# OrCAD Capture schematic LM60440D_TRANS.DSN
size E; title: LM60440D 3.8-V to 36-V, 4-A Ultra-Small Synchronous; rev: 1.0; note: Datasheet:SNVSBN5     EVM:NA; note: Synchronous Step Down Converter
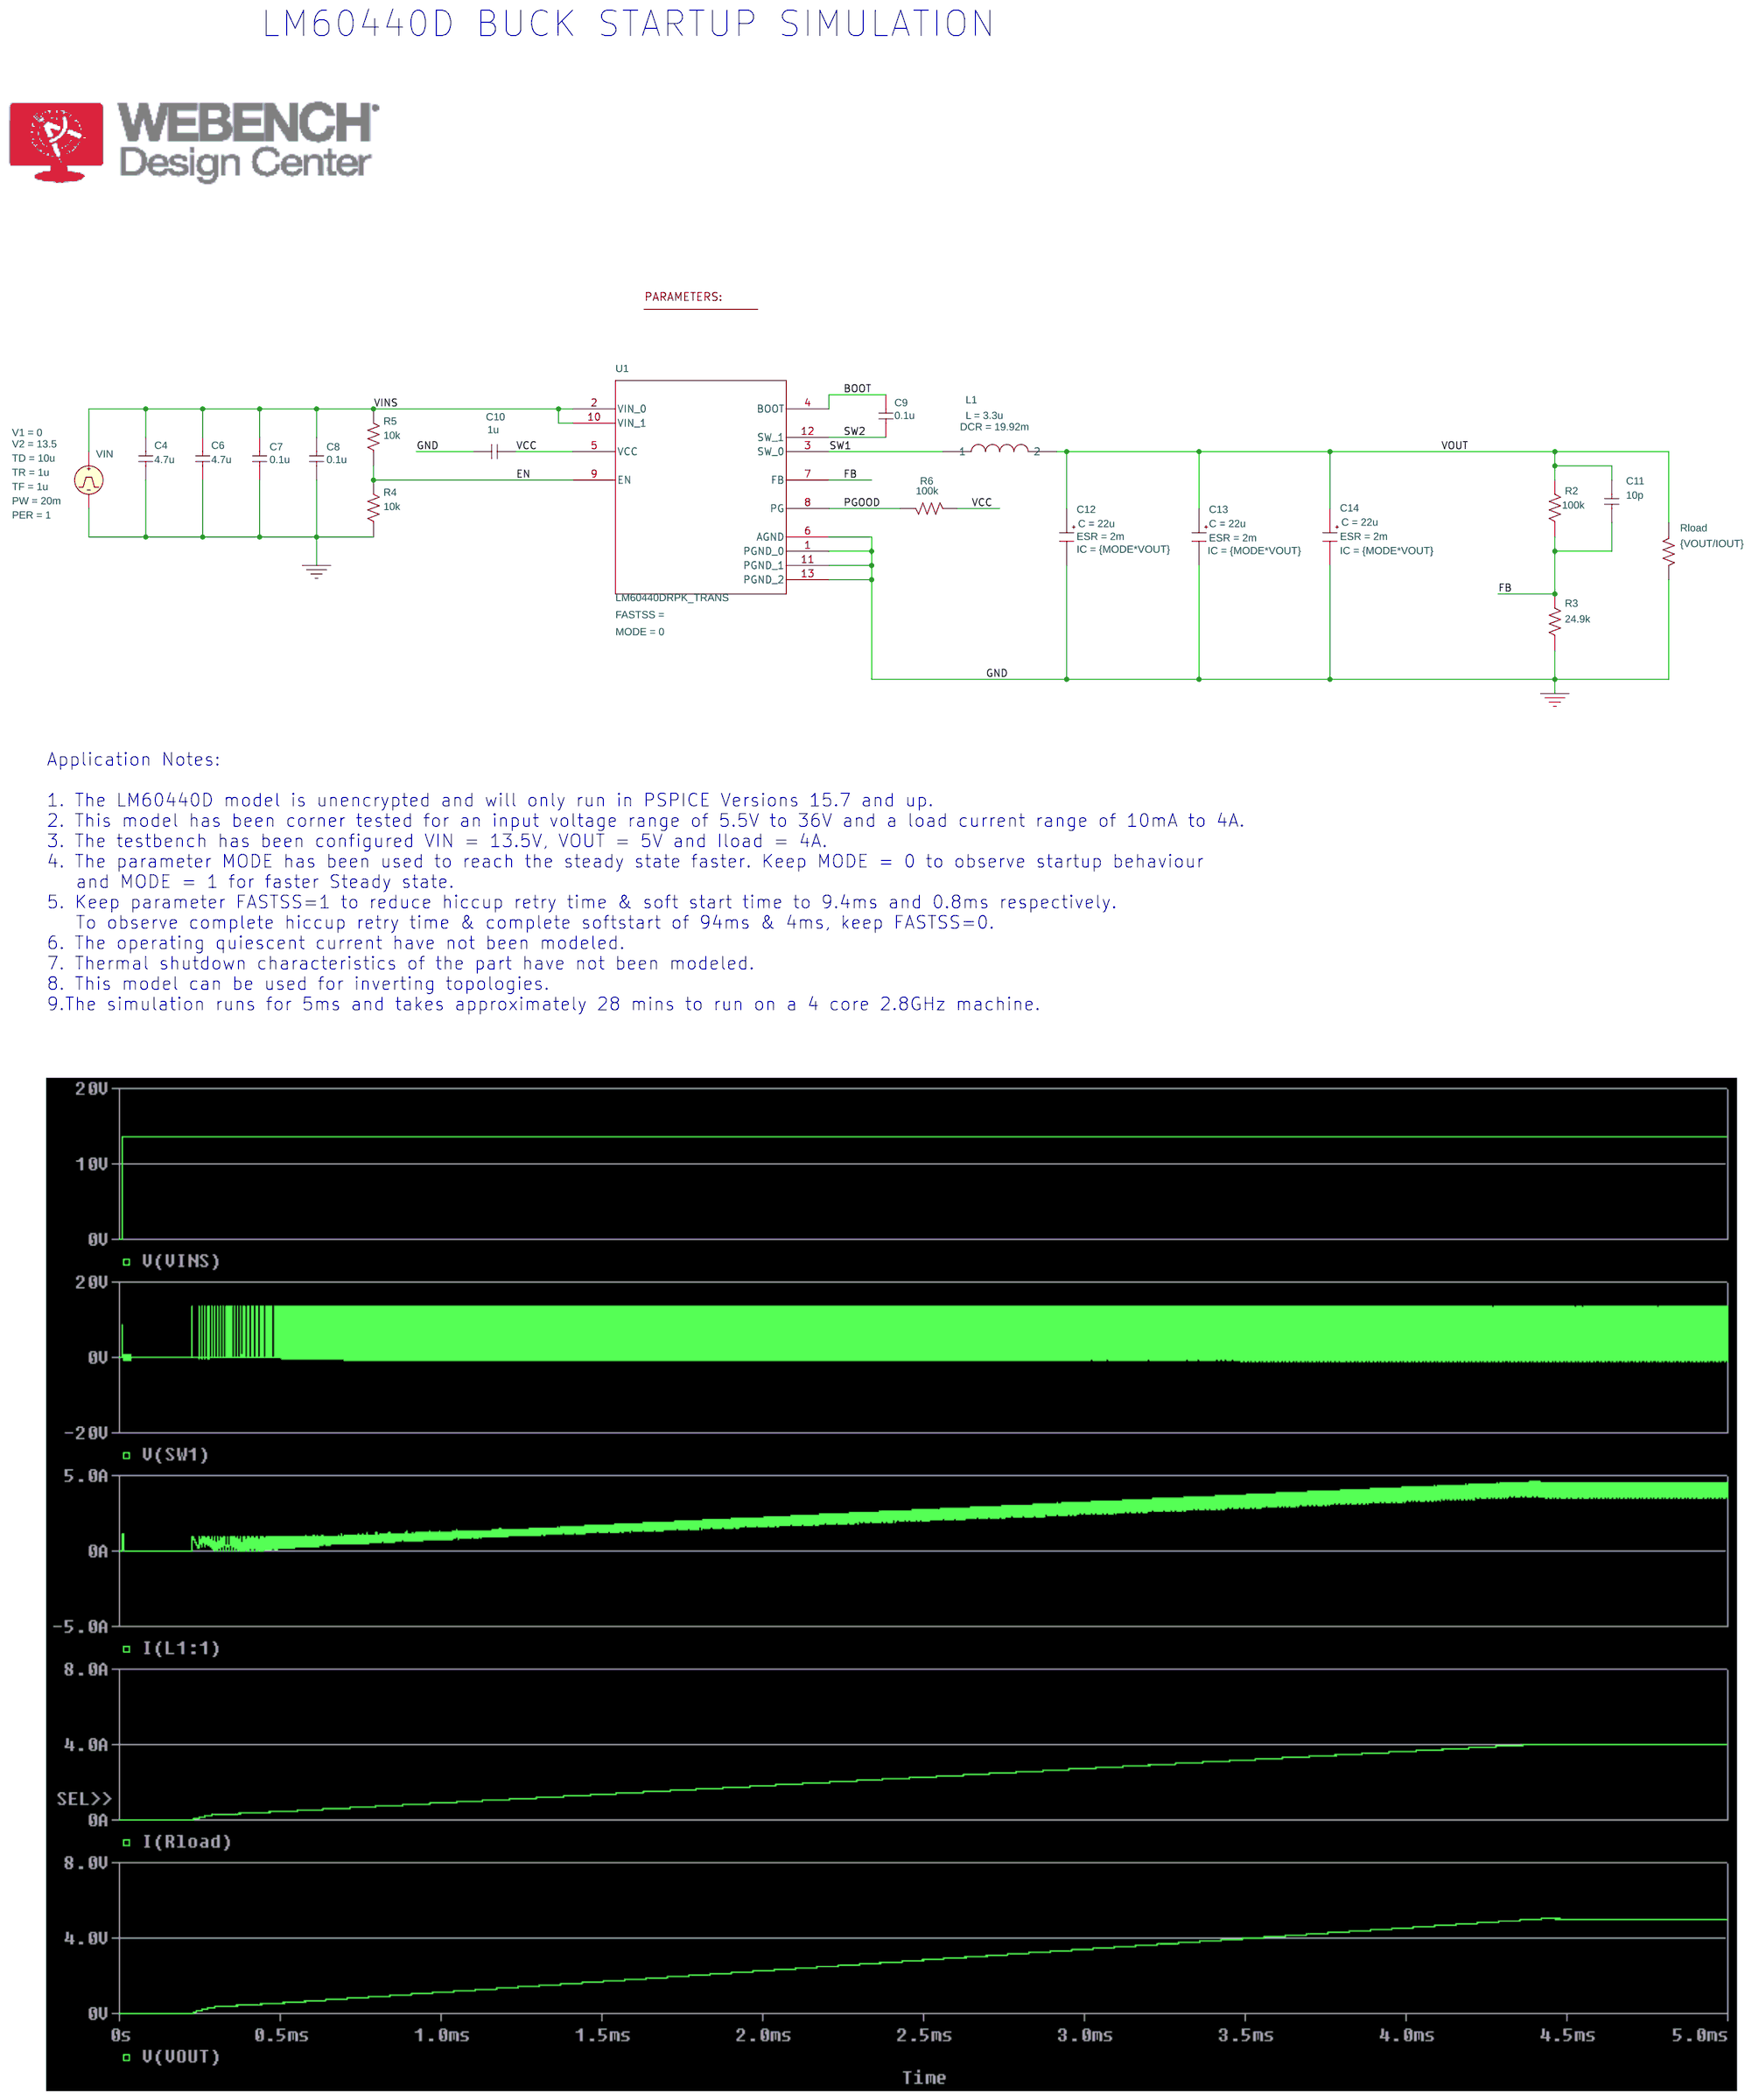
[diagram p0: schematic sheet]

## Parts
1  PARAM
C4  4.7u  [RAD/CK05]
C6  4.7u  [RAD/CK05]
C7  0.1u  [RAD/CK05]
C8  0.1u  [RAD/CK05]
C9  0.1u  [RAD/CK05]
C10  1u  [RAD/CK05]
C11  10p  [RAD/CK05]
C12  CESR
C13  CESR
C14  CESR
L1  LDCR
R2  100k  [AX/RC05]
R3  24.9k  [AX/RC05]
R4  10k  [AX/RC05]
R5  10k  [AX/RC05]
R6  100k  [AX/RC05]
Rload  {VOUT/IOUT}  [AX/RC05]
U1  LM60440DRPK_TRANS  [RPK0013A-MFG]
VIN  VPULSE

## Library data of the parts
1 = PARAM: FASTSS: 0; IOUT: 4; MODE: 0; VIN: 13.5; VOUT: 5
C4 C6-C11 = C
C12-C14 = CESR_0: C: 22u; ESR: 2m; IC: {MODE*VOUT}; PSpiceTemplate: X^@REFDES %IN %OUT @MODEL PARAMS:  ?C|C=@C||C=100u|  ?ESR|ESR=@ESR||ESR=0.01| ?X|X=@X||X=2|  ?IC|IC=@IC||IC=2|; X: 1
L1 = LDCR: DCR: 19.92m; L: 3.3u
R2-R6 Rload = R
U1 = LM60440DRPK_TRANS: MODE: 0
VIN = VPULSE: PER: 1; PW: 20m; TD: 10u; TF: 1u; TR: 1u; V1: 0; V2: 13.5

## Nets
VCC: C10.1 R6.2 U1.5(VCC)
VINS: C4.2 C6.2 C7.2 C8.2 R5.2 U1.2(VIN_0) U1.10(VIN_1) VIN.1(+)
0: C4.1 C6.1 C7.1 C8.1 C10.2 C12.2(OUT) C13.2(OUT) C14.2(OUT) R3.1 R4.1 Rload.2 U1.1(PGND_0) U1.6(AGND) U1.11(PGND_1) U1.13(PGND_2) VIN.2(-)
BOOT: C9.2 U1.4(BOOT)
EN: R4.2 R5.1 U1.9(EN)
FB: C11.2 R2.1 R3.2 U1.7(FB)
PGOOD: R6.1 U1.8(PG)
SW1: L1.1 U1.3(SW_0)
SW2: C9.1 U1.12(SW_1)
VOUT: C11.1 C12.1(IN) C13.1(IN) C14.1(IN) L1.2 R2.2 Rload.1

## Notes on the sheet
- LM60440D BUCK STARTUP SIMULATION
- Application Notes:
  1. The LM60440D model is unencrypted and will only run in PSPICE Versions 15.7 and up.
  2. This model has been corner tested for an input voltage range of 5.5V to 36V and a load current range of 10mA to 4A.
  3. The testbench has been configured VIN = 13.5V, VOUT = 5V and Iload = 4A.
  4. The parameter MODE has been used to reach the steady state faster. Keep MODE = 0 to observe startup behaviour
     and MODE = 1 for faster Steady state.
  5. Keep parameter FASTSS=1 to reduce hiccup retry time & soft start time to 9.4ms and 0.8ms respectively.
     To observe complete hiccup retry time & complete softstart of 94ms & 4ms, keep FASTSS=0.
  6. The operating quiescent current have not been modeled.
  7. Thermal shutdown characteristics of the part have not been modeled.
  8. This model can be used for inverting topologies.
  9.The simulation runs for 5ms and takes approximately 28 mins to run on a 4 core 2.8GHz machine.
